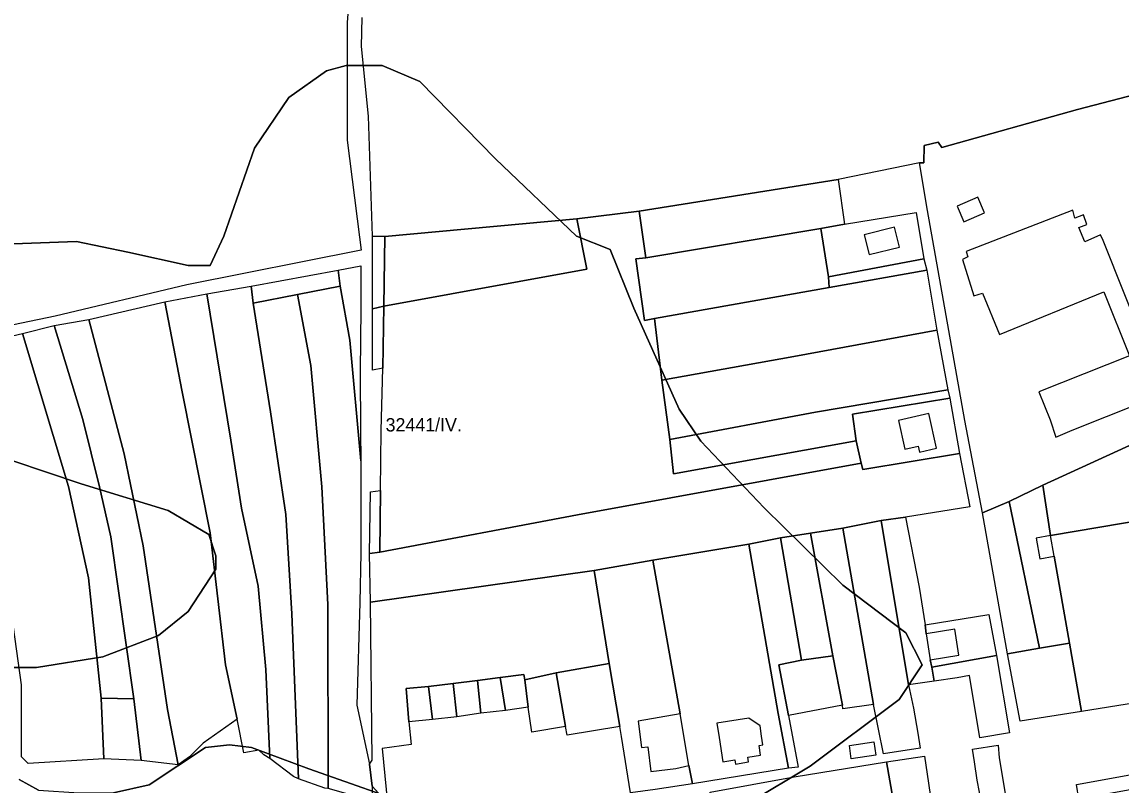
# Model space of a CAD drawing. Extents: x -532083 to -529270, y -1180561 to -1176456.
# Drawn here: x -531552 to -531139.4, y -1178206.1 to -1177919.6 of the extents above; entities that cross this region are included whole.
import ezdxf

# ---------------------------------------------------------------- set-up
doc = ezdxf.new("R2010")
doc.units = 0
for name, color, linetype in [('95560013', 7, 'Continuous'), ('95590013', 7, 'Continuous'), ('95600013', 7, 'Continuous'), ('95610013', 7, 'Continuous'), ('95660013', 7, 'Continuous')]:
    doc.layers.add(name, color=color, linetype=linetype)

msp = doc.modelspace()

# ---------------------------------------------------------------- linework, layer by layer
at = {"layer": '95560013'}
for points in [[(-531424.6003, -1177849.79445), (-531429.9573, -1177919.79245), (-531429.9573, -1177963.95745), (-531425.3063, -1178000.34745), (-531424.6863, -1178005.32445), (-531490.1123, -1178018.25145), (-531539.5053, -1178030.11045), (-531627.5183, -1178048.29445), (-531618.3223, -1178025.89345), (-531615.4323, -1178007.71045), (-531617.5343, -1177984.51945), (-531620.6873, -1177972.92345), (-531635.6623, -1177939.19145), (-531648.2733, -1177911.52045)], [(-531115.2653, -1177942.02045), (-531155.6903, -1177952.50245), (-531206.6683, -1177966.76145), (-531208.0953, -1177964.79345), (-531213.2693, -1177966.04545), (-531213.4483, -1177972.48845), (-531215.0533, -1177972.48845), (-531245.5613, -1177978.75145), (-531320.2903, -1177990.65445), (-531343.7213, -1177993.52145), (-531415.7293, -1178000.11345), (-531420.3633, -1177999.98245), (-531421.9523, -1177954.99745), (-531424.5953, -1177928.77945), (-531424.3013, -1177917.87945)], [(-531112.3683, -1178067.70445), (-531168.7963, -1178093.47545), (-531181.3463, -1178099.60445), (-531191.3503, -1178103.88845), (-531197.9833, -1178069.27145), (-531212.0083, -1177990.43145), (-531215.0533, -1177972.48845), (-531213.4483, -1177972.48845), (-531213.2693, -1177966.04545), (-531208.0953, -1177964.79345), (-531206.6683, -1177966.76145), (-531155.6903, -1177952.50245), (-531115.2653, -1177942.02045)], [(-531129.8783, -1178042.47745), (-531146.1403, -1178001.60145), (-531147.0673, -1177999.52345), (-531152.9813, -1178002.17745), (-531155.1603, -1177996.71345), (-531152.2033, -1177995.62045), (-531153.4483, -1177992.03045), (-531156.7173, -1177993.27945), (-531157.4953, -1177990.31345), (-531197.4933, -1178005.76845), (-531196.8703, -1178007.79745), (-531198.8943, -1178008.73445), (-531194.6913, -1178022.47245), (-531191.4233, -1178021.37945), (-531185.0423, -1178036.99045), (-531145.8383, -1178020.91245), (-531136.2503, -1178045.01245), (-531170.2073, -1178058.52145), (-531166.0453, -1178068.98145), (-531163.8763, -1178075.55045), (-531157.7323, -1178072.85845), (-531106.1623, -1178052.34245)]]:
    msp.add_lwpolyline(points, dxfattribs=at)
for points in [[(-531252.0353, -1177997.14645), (-531317.8033, -1178008.10245), (-531320.2903, -1177990.65445), (-531245.5613, -1177978.75145), (-531243.2043, -1177995.51445)], [(-531193.1033, -1177985.40645), (-531200.9153, -1177988.71545), (-531198.4083, -1177994.63445), (-531190.5963, -1177991.32645)], [(-531343.4223, -1178104.62345), (-531417.6223, -1178118.65445), (-531417.3593, -1178095.46145), (-531417.2023, -1178073.00645), (-531416.6023, -1178049.53045), (-531416.2023, -1178026.25445), (-531340.0043, -1178012.46145), (-531343.7213, -1177993.52145), (-531320.2903, -1177990.65445), (-531317.8033, -1178008.10245), (-531321.5223, -1178008.56945), (-531318.2683, -1178031.64745), (-531314.5503, -1178030.94745), (-531311.7613, -1178054.02645), (-531308.7403, -1178076.40545), (-531307.3463, -1178089.22645), (-531238.7893, -1178076.87145), (-531236.9333, -1178085.22945)], [(-531340.0043, -1178012.46145), (-531416.2023, -1178026.25445), (-531415.7293, -1178000.11345), (-531343.7213, -1177993.52145)], [(-531213.4583, -1178008.56945), (-531249.2473, -1178015.32945), (-531252.0353, -1177997.14645), (-531243.2043, -1177995.51445), (-531216.2473, -1177991.08545)], [(-531249.0143, -1178019.29245), (-531314.5503, -1178030.94745), (-531318.2683, -1178031.64745), (-531321.5223, -1178008.56945), (-531317.8033, -1178008.10245), (-531252.0353, -1177997.14645), (-531249.2473, -1178015.32945)], [(-531222.5463, -1178004.14645), (-531224.3803, -1177996.68045), (-531235.7683, -1177999.47745), (-531233.9343, -1178006.94345)], [(-531212.2963, -1178012.76545), (-531249.0143, -1178019.29245), (-531249.2473, -1178015.32945), (-531213.4583, -1178008.56945)], [(-531432.5263, -1178018.84845), (-531448.5893, -1178021.90445), (-531465.2063, -1178025.23745), (-531466.0373, -1178018.84845), (-531433.3573, -1178012.73645)], [(-531262.2613, -1178045.16745), (-531311.7613, -1178054.02645), (-531314.5503, -1178030.94745), (-531249.0143, -1178019.29245), (-531212.2963, -1178012.76545), (-531208.5783, -1178035.37745)], [(-531475.6163, -1178161.02345), (-531481.3413, -1178111.35345), (-531491.9313, -1178058.52445), (-531498.4403, -1178024.68245), (-531482.6533, -1178021.62645), (-531473.6123, -1178076.61145), (-531469.6053, -1178102.16445), (-531463.3083, -1178131.45045), (-531460.4463, -1178162.74645), (-531458.9153, -1178196.15945), (-531461.2003, -1178194.74945), (-531463.1333, -1178192.98645), (-531468.7573, -1178194.04445), (-531471.2173, -1178181.35045)], [(-531463.3083, -1178131.45045), (-531469.6053, -1178102.16445), (-531473.6123, -1178076.61145), (-531482.6533, -1178021.62645), (-531466.0373, -1178018.84845), (-531465.2063, -1178025.23745), (-531458.7283, -1178065.98845), (-531453.0043, -1178104.46245), (-531450.7143, -1178141.78745), (-531448.1943, -1178203.74145), (-531450.1273, -1178202.85945), (-531458.9153, -1178196.15945), (-531460.4463, -1178162.74645)], [(-531450.7143, -1178141.78745), (-531453.0043, -1178104.46245), (-531458.7283, -1178065.98845), (-531465.2063, -1178025.23745), (-531448.5893, -1178021.90445), (-531443.6043, -1178048.57245), (-531439.4503, -1178094.13245), (-531437.2343, -1178138.30245), (-531437.1223, -1178207.44345), (-531438.3523, -1178207.26745), (-531448.1943, -1178203.74145)], [(-531437.2343, -1178138.30245), (-531439.4503, -1178094.13245), (-531443.6043, -1178048.57245), (-531448.5893, -1178021.90445), (-531432.5263, -1178018.84845), (-531428.9263, -1178039.12745), (-531424.7923, -1178084.35845), (-531424.7923, -1178119.02745), (-531425.2273, -1178137.56245), (-531426.3143, -1178176.15845), (-531421.5013, -1178198.30245), (-531420.5903, -1178206.52645), (-531420.5903, -1178214.14045), (-531425.1713, -1178210.79345), (-531437.1223, -1178207.44345)], [(-531497.3703, -1178177.67545), (-531506.5293, -1178116.23345), (-531513.6853, -1178081.77945), (-531526.9653, -1178031.34945), (-531498.4403, -1178024.68245), (-531491.9313, -1178058.52445), (-531481.3413, -1178111.35345), (-531475.6163, -1178161.02345), (-531471.2173, -1178181.35045), (-531484.0473, -1178190.34145), (-531489.1443, -1178195.45445), (-531493.3623, -1178198.45145)], [(-531200.0493, -1178081.64945), (-531236.3393, -1178087.61645), (-531236.9333, -1178085.22945), (-531238.7893, -1178076.87145), (-531240.1833, -1178066.84745), (-531203.6973, -1178060.78645)], [(-531215.0853, -1178081.06745), (-531208.6693, -1178079.62245), (-531211.5993, -1178066.61445), (-531222.9863, -1178069.17845), (-531220.5513, -1178079.99045), (-531215.5793, -1178078.87145)], [(-531279.1723, -1178115.66345), (-531315.1643, -1178121.63045), (-531337.1753, -1178125.50945), (-531421.1973, -1178137.38545), (-531421.5013, -1178119.11145), (-531417.6223, -1178118.65445), (-531343.4223, -1178104.62345), (-531236.9333, -1178085.22945), (-531236.3393, -1178087.61645), (-531200.0493, -1178081.64945), (-531196.1823, -1178101.64045), (-531220.2763, -1178105.51845), (-531229.4973, -1178106.71245), (-531243.7753, -1178109.69645), (-531255.9703, -1178111.48645), (-531267.2743, -1178113.27645)], [(-531181.9603, -1178156.86045), (-531191.3503, -1178103.88845), (-531181.3463, -1178099.60445), (-531169.9893, -1178154.74145)], [(-531259.4053, -1178159.24645), (-531267.2743, -1178113.27645), (-531255.9703, -1178111.48645), (-531247.6113, -1178157.55645)], [(-531414.8453, -1178212.88345), (-531420.5903, -1178206.52645), (-531421.5013, -1178198.30245), (-531420.5903, -1178196.77945), (-531421.1973, -1178137.38545), (-531337.1753, -1178125.50945), (-531331.5863, -1178160.46445), (-531351.4483, -1178164.02645), (-531363.2533, -1178166.54245), (-531363.5483, -1178164.61845), (-531372.5493, -1178165.65445), (-531380.9593, -1178166.83845), (-531390.1083, -1178168.02245), (-531399.4043, -1178169.05845), (-531407.8153, -1178169.79845), (-531406.7823, -1178182.37945), (-531405.8963, -1178190.81645), (-531416.8123, -1178192.41745)], [(-531244.0003, -1178176.14845), (-531264.2193, -1178180.01145), (-531267.8303, -1178160.93645), (-531259.4053, -1178159.24645), (-531247.6113, -1178157.55645)], [(-531327.5773, -1178184.16545), (-531347.3163, -1178187.41245), (-531347.9073, -1178184.15645), (-531351.4483, -1178164.02645), (-531331.5863, -1178160.46445)], [(-531379.7793, -1178179.12345), (-531388.7803, -1178180.45545), (-531390.1083, -1178168.02245), (-531380.9593, -1178166.83845)], [(-531370.4833, -1178178.08745), (-531379.7793, -1178179.12345), (-531380.9593, -1178166.83845), (-531372.5493, -1178165.65445)], [(-531370.4833, -1178178.08745), (-531372.5493, -1178165.65445), (-531363.5483, -1178164.61845), (-531363.2533, -1178166.54245), (-531361.9253, -1178176.90345)], [(-531347.9073, -1178184.15645), (-531360.5963, -1178186.22845), (-531361.9253, -1178176.90345), (-531363.2533, -1178166.54245), (-531351.4483, -1178164.02645)], [(-531406.7823, -1178182.37945), (-531407.8153, -1178169.79845), (-531399.4043, -1178169.05845), (-531397.9283, -1178181.49145)], [(-531388.7803, -1178180.45545), (-531397.9283, -1178181.49145), (-531399.4043, -1178169.05845), (-531390.1083, -1178168.02245)], [(-531231.4533, -1178194.83245), (-531240.7183, -1178196.28945), (-531241.3513, -1178191.30245), (-531232.2183, -1178189.88945)], [(-531195.3293, -1178306.90545), (-531208.8803, -1178306.09445), (-531222.9713, -1178223.05245), (-531227.3753, -1178197.43345), (-531213.1213, -1178195.27545), (-531210.0303, -1178216.36045), (-531208.9993, -1178221.32245), (-531206.1143, -1178238.68645), (-531188.1853, -1178236.41245), (-531191.2763, -1178217.80745), (-531191.6893, -1178213.26045), (-531193.3343, -1178204.24745), (-531194.3683, -1178197.34345), (-531195.1923, -1178192.58845), (-531185.5063, -1178191.14145), (-531185.1293, -1178195.91445), (-531183.6873, -1178204.80345), (-531181.7973, -1178216.15445), (-531176.0273, -1178251.70945), (-531167.3663, -1178304.49245), (-531184.5043, -1178306.90545)]]:
    msp.add_lwpolyline(points, close=True, dxfattribs=at)
at = {"layer": '95590013'}
for points in [[(-531534.5243, -1178093.95245), (-531551.8913, -1178036.62745), (-531539.9823, -1178033.57145), (-531529.1873, -1178068.89245), (-531522.9413, -1178094.17945), (-531518.6263, -1178112.86045), (-531509.9963, -1178173.68745), (-531522.2603, -1178173.46045), (-531527.0293, -1178128.35245)], [(-531254.1273, -1178066.14845), (-531308.7403, -1178076.40545), (-531311.7613, -1178054.02645), (-531262.2613, -1178045.16745), (-531208.5783, -1178035.37745), (-531204.3943, -1178057.75545)], [(-531238.7893, -1178076.87145), (-531307.3463, -1178089.22645), (-531308.7403, -1178076.40545), (-531254.1273, -1178066.14845), (-531204.3943, -1178057.75545), (-531203.6973, -1178060.78645), (-531240.1833, -1178066.84745)], [(-531102.1233, -1178101.69645), (-531165.8743, -1178112.42545), (-531168.7963, -1178093.47545), (-531112.3683, -1178067.70445)], [(-531158.7233, -1178152.85845), (-531169.9893, -1178154.74145), (-531181.3463, -1178099.60445), (-531168.7963, -1178093.47545), (-531165.8743, -1178112.42545), (-531171.2623, -1178113.43345), (-531169.8103, -1178121.19745), (-531164.4233, -1178120.19045)], [(-531158.7233, -1178152.85845), (-531164.4233, -1178120.19045), (-531165.8743, -1178112.42545), (-531102.1233, -1178101.69645), (-531092.5083, -1178100.27345), (-531129.4843, -1178133.02845), (-531124.8393, -1178154.34945), (-531134.0743, -1178155.90945), (-531131.6993, -1178169.96845), (-531113.7233, -1178166.93245), (-531112.4833, -1178171.69345), (-531120.7303, -1178173.04145), (-531154.2633, -1178178.52145)], [(-531228.5193, -1178194.37145), (-531232.2623, -1178175.80745), (-531243.7753, -1178109.69645), (-531229.4973, -1178106.71245), (-531219.1283, -1178168.53145), (-531217.2423, -1178177.17945), (-531215.6533, -1178186.60845), (-531214.7953, -1178192.28545)], [(-531209.5963, -1178167.04645), (-531219.1283, -1178168.53145), (-531229.4973, -1178106.71245), (-531220.2763, -1178105.51845), (-531215.2113, -1178131.79445), (-531212.9233, -1178145.97845), (-531212.5823, -1178149.34445), (-531210.9933, -1178159.08145), (-531210.4283, -1178161.83145)], [(-531268.0713, -1178179.28645), (-531279.1723, -1178115.66345), (-531267.2743, -1178113.27645), (-531259.4053, -1178159.24645), (-531267.8303, -1178160.93645), (-531264.2193, -1178180.01145), (-531260.6093, -1178199.32645), (-531264.2193, -1178199.80945)], [(-531244.0003, -1178176.14845), (-531247.6113, -1178157.55645), (-531255.9703, -1178111.48645), (-531243.7753, -1178109.69645), (-531232.2623, -1178175.80745), (-531243.7793, -1178177.50345)], [(-531327.5773, -1178184.16545), (-531331.5863, -1178160.46445), (-531337.1753, -1178125.50945), (-531315.1643, -1178121.63045), (-531304.8473, -1178179.32245), (-531320.6263, -1178182.09245), (-531319.4433, -1178191.98545), (-531317.0673, -1178191.70445), (-531315.8873, -1178201.02945), (-531306.5373, -1178199.84545), (-531301.6913, -1178198.71245), (-531300.3103, -1178205.63745), (-531314.3153, -1178207.81345), (-531323.5853, -1178209.00045), (-531326.9383, -1178187.83045)], [(-531186.0983, -1178157.45145), (-531210.4283, -1178161.83145), (-531210.9933, -1178159.08145), (-531200.2253, -1178157.32445), (-531201.8133, -1178147.58745), (-531212.5823, -1178149.34445), (-531212.9233, -1178145.97845), (-531189.0523, -1178142.11245)], [(-531154.2633, -1178178.52145), (-531177.2663, -1178182.05345), (-531181.9603, -1178156.86045), (-531169.9893, -1178154.74145), (-531158.7233, -1178152.85845)], [(-531192.3363, -1178188.32245), (-531196.2873, -1178164.96045), (-531200.8623, -1178165.79445), (-531209.5963, -1178167.04645), (-531210.4283, -1178161.83145), (-531186.0983, -1178157.45145), (-531181.3153, -1178186.44545)], [(-531507.2703, -1178196.92545), (-531521.3513, -1178196.24145), (-531522.2603, -1178173.46045), (-531509.9963, -1178173.68745)], [(-531266.1263, -1178291.73845), (-531281.5423, -1178286.52645), (-531293.6743, -1178208.82545), (-531262.1623, -1178202.95445), (-531227.3753, -1178197.43345), (-531222.9713, -1178223.05245), (-531208.8803, -1178306.09445), (-531217.9073, -1178304.99045), (-531234.8613, -1178301.89845), (-531251.8143, -1178295.05145), (-531242.5043, -1178256.48745), (-531221.2053, -1178261.05645), (-531219.4483, -1178252.86845), (-531254.4563, -1178245.35845), (-531256.2133, -1178253.54645)], [(-531133.9863, -1178207.47245), (-531155.2133, -1178211.39945), (-531156.0903, -1178205.82545), (-531134.6903, -1178202.00245)]]:
    msp.add_lwpolyline(points, close=True, dxfattribs=at)
at = {"layer": '95600013'}
for points in [[(-531264.2193, -1178199.80945), (-531300.3103, -1178205.63745), (-531301.6913, -1178198.71245), (-531304.8473, -1178179.32245), (-531315.1643, -1178121.63045), (-531279.1723, -1178115.66345), (-531268.0713, -1178179.28645)], [(-531274.6943, -1178194.83445), (-531275.2583, -1178191.21045), (-531273.8443, -1178190.99045), (-531274.3423, -1178187.78945), (-531274.8103, -1178183.87445), (-531279.1433, -1178180.97645), (-531291.1783, -1178182.90845), (-531290.2513, -1178188.22645), (-531288.8273, -1178197.37145), (-531284.3913, -1178196.68145), (-531284.1543, -1178198.20345), (-531279.2013, -1178197.43245), (-531279.4893, -1178195.58045)]]:
    msp.add_lwpolyline(points, close=True, dxfattribs=at)
at = {"layer": '95610013'}
for points in [[(-531420.3633, -1178027.28445), (-531420.3633, -1177999.98245), (-531415.7293, -1178000.11345), (-531416.2023, -1178026.25445)], [(-531428.9263, -1178039.12745), (-531432.5263, -1178018.84845), (-531433.3573, -1178012.73645), (-531424.8033, -1178011.20645), (-531424.7923, -1178027.22745), (-531425.0103, -1178050.77745), (-531424.8643, -1178073.29045), (-531424.7923, -1178084.35845)], [(-531420.3633, -1178050.29245), (-531420.3633, -1178027.28445), (-531416.2023, -1178026.25445), (-531416.6023, -1178049.53045)], [(-531509.9963, -1178173.68745), (-531518.6263, -1178112.86045), (-531522.9413, -1178094.17945), (-531529.1873, -1178068.89245), (-531539.9823, -1178033.57145), (-531526.9653, -1178031.34945), (-531513.6853, -1178081.77945), (-531506.5293, -1178116.23345), (-531497.3703, -1178177.67545), (-531493.3623, -1178198.45145), (-531507.2703, -1178196.92545)], [(-531552.1623, -1178168.49445), (-531558.9753, -1178119.80545), (-531562.9493, -1178090.19245), (-531579.8623, -1178043.01645), (-531551.8913, -1178036.62745), (-531534.5243, -1178093.95245), (-531527.0293, -1178128.35245), (-531522.2603, -1178173.46045), (-531521.3513, -1178196.24145), (-531549.7413, -1178198.06445), (-531552.1623, -1178195.54345)], [(-531421.5013, -1178119.11145), (-531421.1973, -1178095.96245), (-531417.3593, -1178095.46145), (-531417.6223, -1178118.65445)]]:
    msp.add_lwpolyline(points, close=True, dxfattribs=at)
at = {"layer": '95660013'}
for points in [[(-531279.5003, -1178213.00045), (-531256.1253, -1178199.00045), (-531222.6253, -1178174.00045), (-531214.0003, -1178161.00045), (-531220.1253, -1178149.00045), (-531243.8753, -1178131.00045), (-531273.3753, -1178102.00045), (-531297.1253, -1178077.00045), (-531305.3123, -1178065.00045), (-531322.3123, -1178027.00045), (-531331.1253, -1178005.00045), (-531343.8123, -1178000.00045), (-531374.1873, -1177971.00045), (-531402.6253, -1177942.00045), (-531416.8123, -1177936.00045), (-531430.3123, -1177936.00045), (-531437.6873, -1177938.00045), (-531451.8753, -1177948.00045), (-531464.6873, -1177967.00045), (-531476.1873, -1178000.00045), (-531481.3753, -1178011.00045), (-531489.6873, -1178011.00045), (-531512.3123, -1178006.00045), (-531531.5003, -1178002.00045), (-531558.6253, -1178003.00045)], [(-531558.6253, -1178003.00045), (-531531.5003, -1178002.00045), (-531512.3123, -1178006.00045), (-531489.6873, -1178011.00045), (-531481.3753, -1178011.00045), (-531476.1873, -1178000.00045), (-531464.6873, -1177967.00045), (-531451.8753, -1177948.00045), (-531437.6873, -1177938.00045), (-531430.3123, -1177936.00045), (-531416.8123, -1177936.00045), (-531402.6253, -1177942.00045), (-531374.1873, -1177971.00045), (-531343.8123, -1178000.00045), (-531331.1253, -1178005.00045), (-531322.3123, -1178027.00045), (-531305.3123, -1178065.00045), (-531297.1253, -1178077.00045), (-531273.3753, -1178102.00045), (-531243.8753, -1178131.00045), (-531220.1253, -1178149.00045), (-531214.0003, -1178161.00045), (-531222.6253, -1178174.00045), (-531256.1253, -1178199.00045), (-531279.5003, -1178213.00045)], [(-531574.8753, -1178162.00045), (-531546.6253, -1178162.00045), (-531521.6873, -1178158.00045), (-531500.8123, -1178150.00045), (-531489.6873, -1178141.00045), (-531479.1873, -1178125.00045), (-531479.1873, -1178120.00045), (-531481.8123, -1178112.00045), (-531497.1253, -1178103.00045), (-531529.8123, -1178093.00045), (-531568.6253, -1178080.00045)], [(-531568.6253, -1178080.00045), (-531529.8123, -1178093.00045), (-531497.1253, -1178103.00045), (-531481.8123, -1178112.00045), (-531479.1873, -1178120.00045), (-531479.1873, -1178125.00045), (-531489.6873, -1178141.00045), (-531500.8123, -1178150.00045), (-531521.6873, -1178158.00045), (-531546.6253, -1178162.00045), (-531574.8753, -1178162.00045)], [(-531553.1253, -1178204.00045), (-531545.8123, -1178208.00045), (-531530.6253, -1178209.00045), (-531517.6873, -1178209.00045), (-531504.3123, -1178206.00045), (-531483.1253, -1178192.00045), (-531474.1253, -1178191.00045), (-531465.8123, -1178192.00045), (-531444.3753, -1178200.00045), (-531401.6873, -1178215.00045), (-531356.8123, -1178222.00045), (-531320.5003, -1178232.00045), (-531310.1253, -1178236.00045), (-531292.1873, -1178242.00045), (-531252.5003, -1178260.00045), (-531236.1253, -1178265.00045), (-531210.6253, -1178270.00045), (-531190.5003, -1178271.00045), (-531166.8123, -1178265.00045), (-531146.3753, -1178255.00045), (-531108.8753, -1178232.00045)], [(-531401.6873, -1178215.00045), (-531444.3753, -1178200.00045), (-531465.8123, -1178192.00045), (-531474.1253, -1178191.00045), (-531483.1253, -1178192.00045), (-531504.3123, -1178206.00045), (-531517.6873, -1178209.00045)], [(-531545.8123, -1178208.00045), (-531553.1253, -1178204.00045)]]:
    msp.add_lwpolyline(points, dxfattribs=at)

# ---------------------------------------------------------------- texts
msp.add_text('32441/IV.', height=5, rotation=0, dxfattribs=at).set_placement((-531415.5003, -1178073.35103))

doc.saveas('drawing.dxf')
